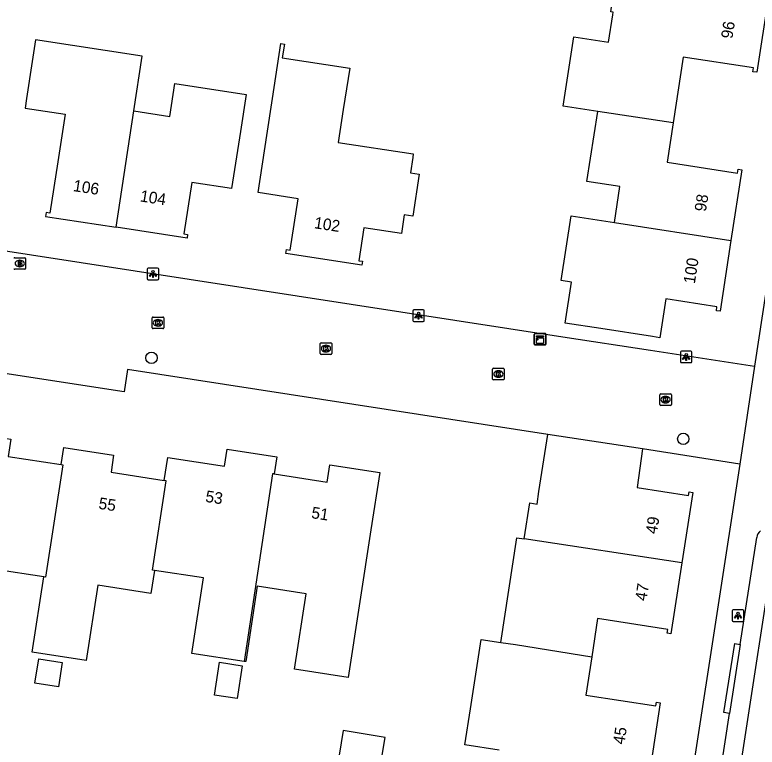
# Model space of a CAD drawing. Extents: x 161486 to 162249, y 379484 to 380829.
# Drawn here: x 161874.7 to 161938.8, y 380678.3 to 380741.6 of the extents above; entities that cross this region are included whole.
import ezdxf

# ---------------------------------------------------------------- set-up
doc = ezdxf.new("R2010")
doc.units = 0
for name, color, linetype in [('IMGEO_Boom', 7, 'Continuous'), ('IMGEO_Brandkraan', 7, 'Continuous'), ('IMGEO_Kast', 7, 'Continuous'), ('IMGEO_Kolk', 7, 'Continuous'), ('IMGEO_Lichtpunt', 7, 'Continuous'), ('IMGEO_Pand', 7, 'Continuous'), ('IMGEO_Pand_nummerreeks', 7, 'Continuous'), ('IMGEO_Rijbaan_lokaal_open', 7, 'Continuous'), ('IMGEO_Voetpad_open', 7, 'Continuous')]:
    doc.layers.add(name, color=color, linetype=linetype)

msp = doc.modelspace()

# ---------------------------------------------------------------- linework, layer by layer
at = {"layer": 'IMGEO_Boom'}
for centre in [(161886.481, 380711.976), (161932.436, 380704.97)]:
    msp.add_circle(centre, 0.489, dxfattribs=at)
at = {"layer": 'IMGEO_Brandkraan'}
for p, q in [((161874.674, 380720.624), (161875.526, 380720.624)), ((161875.087, 380720.404), (161875.112, 380720.404)), ((161875.6, 380720.55), (161875.6, 380719.698)), ((161875.11, 380719.844), (161875.085, 380719.844)), ((161875.526, 380719.624), (161874.674, 380719.624))]:
    msp.add_line(p, q, dxfattribs=at)
for points in [[(161874.674, 380720.624), (161875.526, 380720.624)], [(161874.947, 380720.324), (161874.947, 380719.924), (161875.16, 380719.924)], [(161875.178, 380720.324), (161874.947, 380720.324)], [(161875.6, 380720.55), (161875.6, 380719.698)], [(161875.126, 380720.243), (161875.072, 380720.243), (161875.072, 380720.167)], [(161875.072, 380720.167), (161875.125, 380720.167)], [(161875.134, 380720.091), (161875.072, 380720.091), (161875.072, 380720.01)], [(161875.072, 380720.01), (161875.134, 380720.01)], [(161875.526, 380719.624), (161874.674, 380719.624)]]:
    msp.add_lwpolyline(points, dxfattribs=at)
for centre, radius, start, end in [((161874.676, 380720.548), 0.0765, 91.55205, 178.44795), ((161874.676, 380720.548), 0.0765, 91.55205, 178.44795), ((161875.182, 380720.179), 0.145, 59.4692, 91.53667), ((161875.207, 380720.226), 0.0922, 285.51372, 58.15012), ((161875.524, 380720.548), 0.0765, 1.55205, 88.44795), ((161875.524, 380720.548), 0.0765, 1.55205, 88.44795), ((161874.676, 380719.7), 0.0765, 181.55205, 268.44795), ((161874.676, 380719.7), 0.0765, 181.55205, 268.44795), ((161875.127, 380720.205), 0.0379, 267.82845, 90.93552), ((161875.135, 380720.05), 0.0404, 269.87594, 90.50774), ((161875.166, 380720.175), 0.251, 268.66757, 293.53466), ((161875.212, 380720.034), 0.105, 301.31148, 78.98903), ((161875.524, 380719.7), 0.0765, 271.55205, 358.44795), ((161875.524, 380719.7), 0.0765, 271.55205, 358.44795)]:
    msp.add_arc(centre, radius, start, end, dxfattribs=at)
for centre, major_axis, ratio, start_param, end_param in [((161875.086, 380720.124), (-0.387, 0.002), 0.722429, 4.712389, 7.853982), ((161875.111, 380720.124), (-0.39, 0.002), 0.717154, 1.570796, 4.712389)]:
    msp.add_ellipse(centre, major_axis=major_axis, ratio=ratio, start_param=start_param, end_param=end_param, dxfattribs=at)
at = {"layer": 'IMGEO_Kast'}
for p, q in [((161919.561, 380713.157), (161919.561, 380713.998)), ((161919.561, 380713.998), (161919.561, 380713.157)), ((161919.636, 380714.082), (161920.477, 380714.082)), ((161920.477, 380714.082), (161919.636, 380714.082)), ((161920.561, 380714.007), (161920.561, 380713.166)), ((161920.561, 380713.166), (161920.561, 380714.007)), ((161920.486, 380713.082), (161919.645, 380713.082)), ((161919.645, 380713.082), (161920.486, 380713.082))]:
    msp.add_line(p, q, dxfattribs=at)
for points in [[(161919.756, 380713.872), (161920.356, 380713.872), (161920.356, 380713.787), (161919.756, 380713.787), (161919.756, 380713.872)], [(161919.756, 380713.697), (161920.356, 380713.697), (161920.356, 380713.208), (161919.756, 380713.208), (161919.756, 380713.697)]]:
    msp.add_lwpolyline(points, dxfattribs=at)
msp.add_circle((161919.84, 380713.546), 0.0377, dxfattribs=at)
for centre, start, end in [((161919.639, 380714.004), 92.4484, 184.28452), ((161919.639, 380714.004), 92.4484, 184.28452), ((161920.483, 380714.004), 2.4484, 94.28452), ((161920.483, 380714.004), 2.4484, 94.28452), ((161919.639, 380713.16), 182.4484, 274.28452), ((161919.639, 380713.16), 182.4484, 274.28452), ((161920.483, 380713.16), 272.4484, 4.28452), ((161920.483, 380713.16), 272.4484, 4.28452)]:
    msp.add_arc(centre, 0.0779, start, end, dxfattribs=at)
at = {"layer": 'IMGEO_Kolk'}
for p, q in [((161886.539, 380714.569), (161886.539, 380715.421)), ((161886.614, 380715.495), (161887.466, 380715.495)), ((161887.027, 380715.275), (161887.052, 380715.275)), ((161887.54, 380715.421), (161887.54, 380714.569)), ((161887.05, 380714.715), (161887.025, 380714.715)), ((161887.466, 380714.495), (161886.614, 380714.495)), ((161901.134, 380713.275), (161901.986, 380713.275)), ((161901.059, 380712.349), (161901.059, 380713.201)), ((161901.547, 380713.055), (161901.572, 380713.055)), ((161902.06, 380713.201), (161902.06, 380712.349)), ((161901.986, 380712.275), (161901.134, 380712.275)), ((161901.57, 380712.495), (161901.545, 380712.495)), ((161915.959, 380710.142), (161915.959, 380710.994)), ((161916.034, 380711.068), (161916.886, 380711.068)), ((161916.447, 380710.848), (161916.472, 380710.848)), ((161916.96, 380710.994), (161916.96, 380710.142)), ((161916.886, 380710.068), (161916.034, 380710.068)), ((161916.47, 380710.288), (161916.445, 380710.288)), ((161930.407, 380707.936), (161930.407, 380708.788)), ((161930.482, 380708.862), (161931.334, 380708.862)), ((161931.408, 380708.788), (161931.408, 380707.936)), ((161930.918, 380708.082), (161930.893, 380708.082)), ((161930.895, 380708.642), (161930.92, 380708.642)), ((161931.334, 380707.862), (161930.482, 380707.862))]:
    msp.add_line(p, q, dxfattribs=at)
for points in [[(161886.539, 380714.569), (161886.539, 380715.421)], [(161886.614, 380715.495), (161887.466, 380715.495)], [(161886.86, 380715.195), (161886.983, 380715.195), (161886.983, 380715.044), (161887.113, 380715.195), (161887.277, 380715.195), (161887.131, 380715.044), (161887.284, 380714.795), (161887.132, 380714.795), (161887.047, 380714.959), (161886.983, 380714.892), (161886.983, 380714.795), (161886.86, 380714.795), (161886.86, 380715.195)], [(161887.54, 380715.421), (161887.54, 380714.569)], [(161887.466, 380714.495), (161886.614, 380714.495)], [(161901.134, 380713.275), (161901.986, 380713.275)], [(161901.059, 380712.349), (161901.059, 380713.201)], [(161901.38, 380712.975), (161901.503, 380712.975), (161901.503, 380712.824), (161901.633, 380712.975), (161901.797, 380712.975), (161901.651, 380712.824), (161901.804, 380712.575), (161901.652, 380712.575), (161901.567, 380712.739), (161901.503, 380712.672), (161901.503, 380712.575), (161901.38, 380712.575), (161901.38, 380712.975)], [(161902.06, 380713.201), (161902.06, 380712.349)], [(161901.986, 380712.275), (161901.134, 380712.275)], [(161915.959, 380710.142), (161915.959, 380710.994)], [(161916.034, 380711.068), (161916.886, 380711.068)], [(161916.28, 380710.768), (161916.403, 380710.768), (161916.403, 380710.617), (161916.533, 380710.768), (161916.697, 380710.768), (161916.551, 380710.617), (161916.704, 380710.368), (161916.552, 380710.368), (161916.467, 380710.532), (161916.403, 380710.465), (161916.403, 380710.368), (161916.28, 380710.368), (161916.28, 380710.768)], [(161916.96, 380710.994), (161916.96, 380710.142)], [(161916.886, 380710.068), (161916.034, 380710.068)], [(161930.407, 380707.936), (161930.407, 380708.788)], [(161930.482, 380708.862), (161931.334, 380708.862)], [(161931.408, 380708.788), (161931.408, 380707.936)], [(161930.728, 380708.562), (161930.851, 380708.562), (161930.851, 380708.411), (161930.981, 380708.562), (161931.145, 380708.562), (161930.999, 380708.411), (161931.152, 380708.162), (161931, 380708.162), (161930.915, 380708.326), (161930.851, 380708.259), (161930.851, 380708.162), (161930.728, 380708.162), (161930.728, 380708.562)], [(161931.334, 380707.862), (161930.482, 380707.862)]]:
    msp.add_lwpolyline(points, dxfattribs=at)
for centre, start, end in [((161886.616, 380715.419), 91.55205, 178.44795), ((161886.616, 380715.419), 91.55205, 178.44795), ((161887.464, 380715.419), 1.55205, 88.44795), ((161887.464, 380715.419), 1.55205, 88.44795), ((161886.616, 380714.571), 181.55205, 268.44795), ((161886.616, 380714.571), 181.55205, 268.44795), ((161887.464, 380714.571), 271.55205, 358.44795), ((161887.464, 380714.571), 271.55205, 358.44795), ((161901.136, 380713.199), 91.55205, 178.44795), ((161901.136, 380713.199), 91.55205, 178.44795), ((161901.984, 380713.199), 1.55205, 88.44795), ((161901.984, 380713.199), 1.55205, 88.44795), ((161901.136, 380712.351), 181.55205, 268.44795), ((161901.136, 380712.351), 181.55205, 268.44795), ((161901.984, 380712.351), 271.55205, 358.44795), ((161901.984, 380712.351), 271.55205, 358.44795), ((161916.036, 380710.992), 91.55205, 178.44795), ((161916.036, 380710.992), 91.55205, 178.44795), ((161916.884, 380710.992), 1.55205, 88.44795), ((161916.884, 380710.992), 1.55205, 88.44795), ((161916.036, 380710.144), 181.55205, 268.44795), ((161916.036, 380710.144), 181.55205, 268.44795), ((161916.884, 380710.144), 271.55205, 358.44795), ((161916.884, 380710.144), 271.55205, 358.44795), ((161930.484, 380708.786), 91.55205, 178.44795), ((161930.484, 380708.786), 91.55205, 178.44795), ((161931.332, 380708.786), 1.55205, 88.44795), ((161931.332, 380708.786), 1.55205, 88.44795), ((161930.484, 380707.938), 181.55205, 268.44795), ((161930.484, 380707.938), 181.55205, 268.44795), ((161931.332, 380707.938), 271.55205, 358.44795), ((161931.332, 380707.938), 271.55205, 358.44795)]:
    msp.add_arc(centre, 0.0765, start, end, dxfattribs=at)
for centre, major_axis, ratio, start_param, end_param in [((161887.026, 380714.995), (-0.387, 0.002), 0.722429, 4.712389, 7.853982), ((161887.051, 380714.995), (-0.39, 0.002), 0.717154, 1.570796, 4.712389), ((161901.546, 380712.775), (-0.387, 0.002), 0.722429, 4.712389, 7.853982), ((161901.571, 380712.775), (-0.39, 0.002), 0.717154, 1.570796, 4.712389), ((161916.446, 380710.568), (-0.387, 0.002), 0.722429, 4.712389, 7.853982), ((161916.471, 380710.568), (-0.39, 0.002), 0.717154, 1.570796, 4.712389), ((161930.894, 380708.362), (-0.387, 0.002), 0.722429, 4.712389, 7.853982), ((161930.919, 380708.362), (-0.39, 0.002), 0.717154, 1.570796, 4.712389)]:
    msp.add_ellipse(centre, major_axis=major_axis, ratio=ratio, start_param=start_param, end_param=end_param, dxfattribs=at)
at = {"layer": 'IMGEO_Lichtpunt'}
for p, q in [((161886.111, 380719.626), (161886.111, 380718.819)), ((161886.111, 380719.626), (161886.111, 380718.819)), ((161887.013, 380719.721), (161886.205, 380719.721)), ((161887.013, 380719.721), (161886.205, 380719.721)), ((161887.107, 380718.819), (161887.107, 380719.626)), ((161887.107, 380718.819), (161887.107, 380719.626)), ((161886.205, 380718.725), (161887.013, 380718.725)), ((161886.205, 380718.725), (161887.013, 380718.725)), ((161909.06, 380716.017), (161909.06, 380715.21)), ((161909.06, 380716.017), (161909.06, 380715.21)), ((161909.962, 380716.112), (161909.154, 380716.112)), ((161909.962, 380716.112), (161909.154, 380716.112)), ((161910.056, 380715.21), (161910.056, 380716.017)), ((161910.056, 380715.21), (161910.056, 380716.017)), ((161909.154, 380715.116), (161909.962, 380715.116)), ((161909.154, 380715.116), (161909.962, 380715.116)), ((161932.186, 380712.457), (161932.186, 380711.65)), ((161932.186, 380712.457), (161932.186, 380711.65)), ((161933.088, 380712.552), (161932.28, 380712.552)), ((161933.088, 380712.552), (161932.28, 380712.552)), ((161933.182, 380711.65), (161933.182, 380712.457)), ((161933.182, 380711.65), (161933.182, 380712.457)), ((161932.28, 380711.556), (161933.088, 380711.556)), ((161932.28, 380711.556), (161933.088, 380711.556)), ((161937.565, 380690.192), (161936.757, 380690.192)), ((161937.565, 380690.192), (161936.757, 380690.192)), ((161936.663, 380690.097), (161936.663, 380689.29)), ((161936.663, 380690.097), (161936.663, 380689.29)), ((161937.659, 380689.29), (161937.659, 380690.097)), ((161937.659, 380689.29), (161937.659, 380690.097)), ((161936.757, 380689.196), (161937.565, 380689.196)), ((161936.757, 380689.196), (161937.565, 380689.196))]:
    msp.add_line(p, q, dxfattribs=at)
for points in [[(161886.485, 380719.29), (161886.524, 380719.262), (161886.336, 380719), (161886.298, 380719.027), (161886.485, 380719.29)], [(161886.587, 380719.242), (161886.634, 380719.242), (161886.634, 380718.92), (161886.587, 380718.92), (161886.587, 380719.242)], [(161886.697, 380719.262), (161886.735, 380719.289), (161886.922, 380719.027), (161886.883, 380718.999), (161886.697, 380719.262)], [(161909.434, 380715.681), (161909.473, 380715.653), (161909.285, 380715.391), (161909.247, 380715.418), (161909.434, 380715.681)], [(161909.536, 380715.633), (161909.583, 380715.633), (161909.583, 380715.311), (161909.536, 380715.311), (161909.536, 380715.633)], [(161909.646, 380715.653), (161909.684, 380715.68), (161909.871, 380715.418), (161909.832, 380715.39), (161909.646, 380715.653)], [(161932.56, 380712.121), (161932.599, 380712.093), (161932.411, 380711.831), (161932.373, 380711.858), (161932.56, 380712.121)], [(161932.662, 380712.073), (161932.709, 380712.073), (161932.709, 380711.751), (161932.662, 380711.751), (161932.662, 380712.073)], [(161932.772, 380712.093), (161932.81, 380712.12), (161932.997, 380711.858), (161932.958, 380711.83), (161932.772, 380712.093)], [(161937.037, 380689.761), (161937.076, 380689.733), (161936.888, 380689.471), (161936.85, 380689.498), (161937.037, 380689.761)], [(161937.139, 380689.713), (161937.186, 380689.713), (161937.186, 380689.391), (161937.139, 380689.391), (161937.139, 380689.713)], [(161937.249, 380689.733), (161937.287, 380689.76), (161937.474, 380689.498), (161937.435, 380689.47), (161937.249, 380689.733)]]:
    msp.add_lwpolyline(points, dxfattribs=at)
for centre in [(161886.61, 380719.424), (161909.559, 380715.815), (161932.685, 380712.255), (161937.162, 380689.895)]:
    msp.add_circle(centre, 0.0994, dxfattribs=at)
for centre, start, end in [((161886.205, 380719.626), 90, 180), ((161886.205, 380719.626), 90, 180), ((161887.013, 380719.626), 0, 90), ((161887.013, 380719.626), 0, 90), ((161886.205, 380718.819), 180, 270), ((161886.205, 380718.819), 180, 270), ((161887.013, 380718.819), 270, 0), ((161887.013, 380718.819), 270, 360), ((161909.154, 380716.017), 90, 180), ((161909.154, 380716.017), 90, 180), ((161909.962, 380716.017), 0, 90), ((161909.962, 380716.017), 0, 90), ((161909.154, 380715.21), 180, 270), ((161909.154, 380715.21), 180, 270), ((161909.962, 380715.21), 270, 0), ((161909.962, 380715.21), 270, 360), ((161932.28, 380712.457), 90, 180), ((161932.28, 380712.457), 90, 180), ((161933.088, 380712.457), 0, 90), ((161933.088, 380712.457), 0, 90), ((161932.28, 380711.65), 180, 270), ((161932.28, 380711.65), 180, 270), ((161933.088, 380711.65), 270, 0), ((161933.088, 380711.65), 270, 360), ((161936.757, 380690.097), 90, 180), ((161936.757, 380690.097), 90, 180), ((161937.565, 380690.097), 0, 90), ((161937.565, 380690.097), 0, 90), ((161936.757, 380689.29), 180, 270), ((161936.757, 380689.29), 180, 270), ((161937.565, 380689.29), 270, 0), ((161937.565, 380689.29), 270, 360)]:
    msp.add_arc(centre, 0.0946, start, end, dxfattribs=at)
at = {"layer": 'IMGEO_Pand'}
for points in [[(161925.038, 380733.264), (161922.06, 380733.719), (161922.983, 380739.709), (161925.971, 380739.249), (161926.334, 380741.606), (161926.369, 380741.832), (161926.166, 380741.862), (161926.734, 380745.548), (161927.761, 380745.389), (161927.832, 380745.853), (161938.822, 380744.157), (161938.654, 380743.069), (161939.424, 380742.95), (161939.474, 380743.275), (161939.8, 380743.225), (161938.78, 380736.645), (161938.454, 380736.695), (161938.504, 380737.02), (161932.437, 380737.949), (161931.563, 380732.267)], [(161884.958, 380733.324), (161885.668, 380738.038), (161876.465, 380739.44), (161876.184, 380737.595), (161875.694, 380734.377), (161875.57, 380733.561), (161879.024, 380733.035), (161878.391, 380728.908), (161877.71, 380724.476), (161877.384, 380724.526), (161877.334, 380724.2), (161883.441, 380723.256)], [(161908.856, 380727.946), (161909.598, 380727.834), (161909.056, 380724.215), (161908.314, 380724.326), (161908.074, 380722.724), (161904.828, 380723.21), (161904.39, 380720.366), (161904.716, 380720.316), (161904.666, 380719.99), (161898.094, 380721), (161898.144, 380721.326), (161898.47, 380721.276), (161899.147, 380725.723), (161895.698, 380726.247), (161896.449, 380731.191), (161896.934, 380734.382), (161897.655, 380739.129), (161897.962, 380739.083), (161897.781, 380737.896), (161903.608, 380736.991), (161903.057, 380733.434), (161902.615, 380730.58), (161909.105, 380729.608), (161909.055, 380729.271), (161908.856, 380727.946)], [(161884.958, 380733.324), (161888.069, 380732.842), (161888.509, 380735.687), (161894.662, 380734.734), (161894.166, 380731.535), (161893.4, 380726.594), (161889.959, 380727.127), (161889.28, 380722.686), (161889.606, 380722.636), (161889.556, 380722.31), (161883.441, 380723.256)], [(161883.441, 380723.256), (161884.958, 380733.324)], [(161926.486, 380723.668), (161926.964, 380726.768), (161924.104, 380727.209), (161925.038, 380733.264)], [(161931.563, 380732.267), (161925.038, 380733.264)], [(161931.563, 380732.267), (161931.041, 380728.874), (161937.114, 380727.94), (161937.164, 380728.265), (161937.49, 380728.215), (161936.556, 380722.109)], [(161936.556, 380722.109), (161935.62, 380715.995), (161935.294, 380716.045), (161935.344, 380716.371), (161930.92, 380717.058), (161930.4, 380713.71), (161929.771, 380713.807), (161925.323, 380714.497), (161922.219, 380714.973), (161922.765, 380718.522), (161921.867, 380718.661), (161922.732, 380724.249), (161926.486, 380723.668)], [(161926.486, 380723.668), (161936.556, 380722.109)], [(161870.174, 380705.572), (161874.322, 380704.933), (161874.093, 380703.452), (161878.665, 380702.745)], [(161918.693, 380696.319), (161919.171, 380699.432), (161919.795, 380699.336), (161919.961, 380700.418), (161920.72, 380705.36)], [(161928.91, 380704.1), (161920.72, 380705.36)], [(161878.665, 380702.745), (161878.894, 380704.226), (161883.21, 380703.56), (161882.983, 380702.079), (161887.584, 380701.375)], [(161887.584, 380701.375), (161887.886, 380703.35), (161892.793, 380702.599), (161893.02, 380704.08), (161897.31, 380703.42), (161897.081, 380701.935)], [(161928.91, 380704.1), (161928.44, 380700.76), (161932.894, 380700.07), (161932.944, 380700.395), (161933.27, 380700.345), (161932.316, 380694.245)], [(161878.665, 380702.745), (161878.824, 380702.72), (161877.33, 380693.018), (161877.172, 380693.042)], [(161897.081, 380701.935), (161901.675, 380701.227), (161901.903, 380702.712), (161906.2, 380702.05), (161905.441, 380697.108), (161903.483, 380684.354), (161898.846, 380685.068), (161899.849, 380691.578), (161895.627, 380692.229), (161894.624, 380685.718), (161894.49, 380685.739)], [(161897.081, 380701.935), (161896.928, 380701.959), (161894.49, 380685.739)], [(161886.73, 380693.6), (161886.572, 380693.624), (161887.744, 380701.35), (161887.584, 380701.375)], [(161916.662, 380687.385), (161918.051, 380696.418), (161918.693, 380696.319)], [(161932.316, 380694.245), (161918.693, 380696.319)], [(161932.316, 380694.245), (161931.36, 380688.135), (161931.034, 380688.185), (161931.084, 380688.51), (161925.03, 380689.444), (161924.518, 380686.134)], [(161877.172, 380693.042), (161872.97, 380693.69), (161871.967, 380687.18), (161867.449, 380687.876)], [(161886.73, 380693.6), (161886.425, 380691.618), (161881.848, 380692.323), (161880.845, 380685.812), (161876.169, 380686.532), (161877.172, 380693.042)], [(161894.49, 380685.739), (161889.969, 380686.436), (161890.972, 380692.947), (161886.73, 380693.6)], [(161916.534, 380678.075), (161913.559, 380678.534), (161914.036, 380681.642), (161914.958, 380687.646), (161916.662, 380687.385)], [(161916.662, 380687.385), (161917.93, 380687.19), (161924.518, 380686.134)], [(161876.733, 380685.966), (161878.759, 380685.654), (161878.434, 380683.543), (161876.408, 380683.855), (161876.733, 380685.966)], [(161891.914, 380682.828), (161892.351, 380685.663), (161894.324, 380685.358), (161893.887, 380682.524), (161891.914, 380682.828)], [(161924.518, 380686.134), (161924.006, 380682.826), (161930.071, 380681.887), (161930.121, 380682.212), (161930.447, 380682.162), (161929.505, 380676.071)], [(161906.668, 380679.16), (161903.048, 380679.761), (161902.314, 380675.338), (161905.934, 380674.737), (161906.668, 380679.16)]]:
    msp.add_lwpolyline(points, dxfattribs=at)
at = {"layer": 'IMGEO_Rijbaan_lokaal_open'}
for points in [[(161806.838, 380731.553), (161922.038, 380713.794), (161929.59, 380712.634), (161938.583, 380711.252)], [(161920.72, 380705.36), (161884.401, 380710.951), (161884.124, 380709.027), (161858.224, 380713.01), (161858.506, 380714.977), (161825.187, 380720.083)], [(161938.583, 380711.252), (161937.319, 380702.795)], [(161937.319, 380702.795), (161928.91, 380704.1)], [(161940.771, 380698.875), (161933.359, 380650.594)]]:
    msp.add_lwpolyline(points, dxfattribs=at)
at = {"layer": 'IMGEO_Voetpad_open'}
for points in [[(161955.926, 380742.626), (161955.778, 380742.035), (161945.932, 380743.53), (161945.58, 380741.467), (161943.256, 380741.795), (161938.583, 380711.252)], [(161937.319, 380702.795), (161927.438, 380638.646)], [(161937.356, 380687.202), (161938.782, 380696.459)], [(161936.438, 380681.248), (161935.925, 380681.331), (161936.89, 380687.278), (161937.356, 380687.202)], [(161937.356, 380687.202), (161936.438, 380681.248)], [(161934.552, 380669.005), (161936.438, 380681.248)]]:
    msp.add_lwpolyline(points, dxfattribs=at)
msp.add_arc((161939.546, 380696.385), 0.768, 124.44804, 174.44186, dxfattribs=at)

# ---------------------------------------------------------------- texts
at = {"layer": 'IMGEO_Pand_nummerreeks'}
for s, rotation, p in [('96', 81.18812, (161936.673, 380739.505)), ('106', 351.21083, (161879.665, 380726.39)), ('104', 351.20946, (161885.45, 380725.495)), ('98', 81.29698, (161934.382, 380724.565)), ('102', 351.26301, (161900.489, 380723.181)), ('100', 81.29965, (161933.428, 380718.325)), ('53', 351.24527, (161891.091, 380699.537)), ('55', 351.24639, (161881.86, 380698.937)), ('51', 351.24527, (161900.246, 380698.128)), ('49', 81.10932, (161930.15, 380696.703)), ('47', 81.10791, (161929.246, 380690.922)), ('45', 81.21104, (161927.334, 380678.518))]:
    msp.add_text(s, height=1, rotation=rotation, dxfattribs=at).set_placement(p)

doc.saveas('drawing.dxf')
